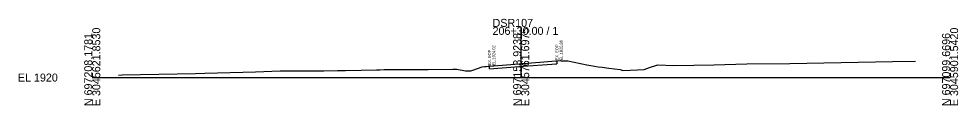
# Model space of a CAD drawing. Extents: x -26 to 19003, y -31 to 24541.
# Drawn here: x 1974.3 to 2302.8, y 10490.3 to 10520.6 of the extents above; entities that cross this region are included whole.
import ezdxf

# ---------------------------------------------------------------- set-up
doc = ezdxf.new("R2010")
doc.units = 0
for name, color, linetype in [('DESIGN - SHEET - Light Grid', 7, 'Continuous'), ('SURVEY - GROUND - Existing Pavement Layer', 7, 'Continuous'), ('SURVEY - GROUND - Existing Pavement Text', 7, 'Continuous'), ('SURVEY - GROUND - Top of Ground', 7, 'Continuous')]:
    doc.layers.add(name, color=color, linetype=linetype)

msp = doc.modelspace()

# ---------------------------------------------------------------- linework, layer by layer
at = {"layer": 'DESIGN - SHEET - Light Grid'}
for p, q in [((2150, 10500), (2150, 10517.75)), ((2000, 10500), (2150, 10500)), ((2150, 10500), (2300, 10500))]:
    msp.add_line(p, q, dxfattribs=at)
at = {"layer": 'SURVEY - GROUND - Existing Pavement Layer'}
for p, q in [((2138.91, 10503.02), (2138.91, 10504.02)), ((2138.91, 10503.02), (2149.34, 10503.85)), ((2149.34, 10503.85), (2150, 10503.9)), ((2150, 10503.9), (2150.78, 10503.96)), ((2150.78, 10503.96), (2160.76, 10504.73)), ((2160.76, 10504.73), (2162.13, 10504.84)), ((2162.13, 10504.84), (2162.49, 10504.86)), ((2162.49, 10505.86), (2162.49, 10504.86))]:
    msp.add_line(p, q, dxfattribs=at)
at = {"layer": 'SURVEY - GROUND - Top of Ground'}
msp.add_lwpolyline([(2009.18, 10500.87), (2010.49, 10500.9), (2036.12, 10501.41), (2039.34, 10501.55), (2057.06, 10502.03), (2065.74, 10502.37), (2075.73, 10502.3), (2076.19, 10502.31), (2080.98, 10502.41), (2085.71, 10502.42), (2088.56, 10502.45), (2094.02, 10502.57), (2099.39, 10502.72), (2100.55, 10502.69), (2102.03, 10502.78), (2114.96, 10502.85), (2117.49, 10502.86), (2126.11, 10502.9), (2127.55, 10502.91), (2130.52, 10502.34), (2132.4, 10502.37), (2133.06, 10502.58), (2136.33, 10503.73), (2137.17, 10503.83), (2137.77, 10503.89), (2138.58, 10503.99), (2138.91, 10504.02), (2149.34, 10504.85), (2150, 10504.9), (2150.78, 10504.96), (2160.76, 10505.73), (2162.13, 10505.84), (2162.49, 10505.86), (2163.65, 10505.92), (2163.99, 10505.9), (2166.34, 10505.89), (2173.02, 10504.46), (2174.4, 10504.2), (2176.91, 10503.72), (2178.28, 10503.67), (2180.69, 10503.26), (2184.66, 10502.84), (2185.51, 10502.52), (2190.66, 10502.69), (2193, 10502.79), (2194.85, 10503.56), (2197.42, 10504.29), (2197.62, 10504.41), (2203.34, 10504.2), (2217.39, 10504.48), (2228.9, 10504.78), (2243.96, 10504.89), (2249.93, 10505.09), (2279.87, 10505.68), (2287.95, 10505.76)], dxfattribs=at)

# ---------------------------------------------------------------- texts
at = {"layer": 'DESIGN - SHEET - Light Grid'}
for s, p in [('DSR107', (2140, 10517.75)), ('206+30.00 / 1', (2140, 10514.95)), ('EL 1920', (1974, 10498.6))]:
    msp.add_text(s, height=2.8, dxfattribs=at).set_placement(p)
for s, p in [('E 3045621.8530', (2002.8, 10490)), ('E 3045761.6975', (2152.8, 10490)), ('E 3045901.5420', (2302.8, 10490)), ('N 697208.1781', (2000, 10490)), ('N 697153.9238', (2150, 10490)), ('N 697099.6696', (2300, 10490))]:
    msp.add_text(s, height=2.8, rotation=90, dxfattribs=at).set_placement(p)
at = {"layer": 'SURVEY - GROUND - Existing Pavement Text'}
for s, p in [('EL.1924.02', (2140.91, 10504.22)), ('EX. EOP', (2162.99, 10506.06)), ('EL.1925.86', (2164.49, 10506.06)), ('EX. EOP', (2139.41, 10504.22))]:
    msp.add_text(s, height=1, rotation=90, dxfattribs=at).set_placement(p)

doc.saveas('drawing.dxf')
